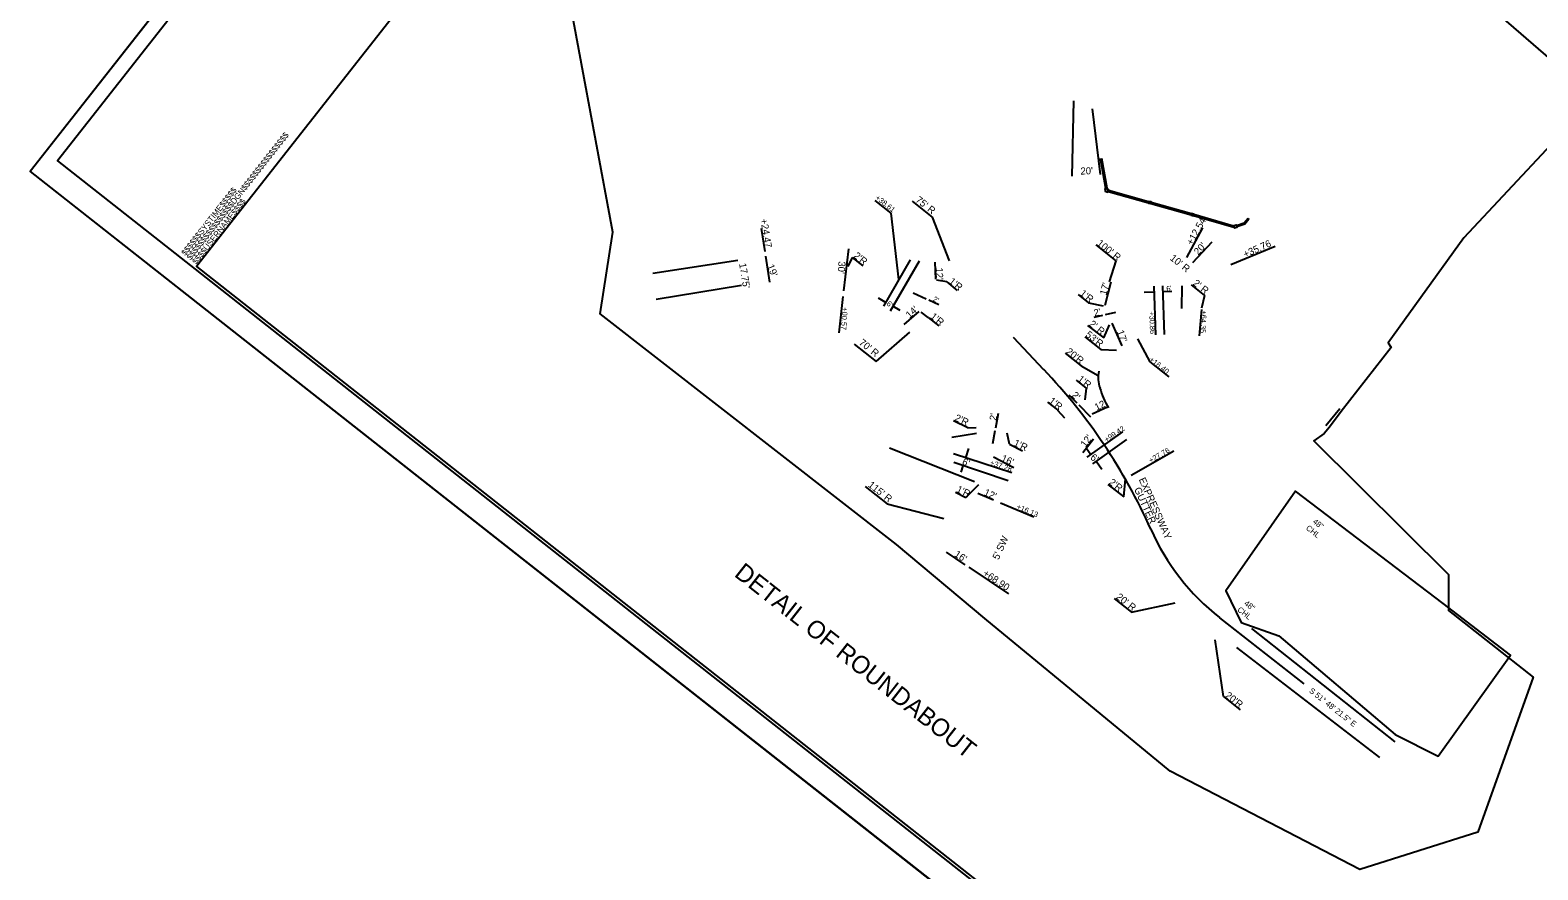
# Model space of a CAD drawing. Extents: x 556999 to 558602, y 505955 to 507732.
# Drawn here: x 556999 to 558063, y 506548 to 507140 of the extents above; entities that cross this region are included whole.
import ezdxf

# ---------------------------------------------------------------- set-up
doc = ezdxf.new("R2010")
doc.units = 0
for name, color, linetype in [('Default', 7, 'Continuous'), ('Exist Roads EOP', 7, 'Continuous'), ('Prop Dimension', 7, 'Continuous'), ('Prop Dimension Text', 7, 'Continuous'), ('Prop Horizontal Alignment', 7, 'Continuous'), ('Prop Horizontal Alignment Direction Label', 7, 'Continuous'), ('Prop Paint Stripe', 7, 'Continuous'), ('Sheet Border Standard 30in CELL', 7, 'Continuous'), ('Sheet Clip Boundary CELL', 7, 'Continuous'), ('Sheet Cutting Line CELL', 7, 'Continuous'), ('Sheet Plot Border Inside CELL', 7, 'Continuous'), ('Sheet Plot Border Outside CELL', 7, 'Continuous')]:
    doc.layers.add(name, color=color, linetype=linetype)

msp = doc.modelspace()

# ---------------------------------------------------------------- linework, layer by layer
at = {"layer": 'Default'}
for p, q in [((557754.1, 507049.3), (557757.8, 507028.2)), ((557755, 507049.4), (557758.7, 507028.4)), ((557759.8, 507025.9), (557788.1, 507017.8)), ((557760, 507026.8), (557788.2, 507018.7)), ((557789.8, 507017.4), (557818.2, 507009.3)), ((557790.1, 507018.3), (557818.5, 507010.2)), ((557820, 507008.8), (557848.5, 507000.6)), ((557820.2, 507009.7), (557848.2, 507001.7))]:
    msp.add_line(p, q, dxfattribs=at)
for points in [[(557757.4, 507027.9), (557757.7, 507026), (557759.5, 507025.4), (557759.9, 507027.1), (557759.1, 507027.2), (557759, 507028.2), (557757.4, 507027.9)], [(557788.2, 507017.6), (557789.7, 507017.3), (557790.1, 507018.4), (557788.5, 507018.8), (557788.2, 507017.6)], [(557818.3, 507009), (557819.9, 507008.6), (557820.2, 507009.7), (557818.6, 507010.2), (557818.3, 507009)], [(557848.3, 507001.8), (557850, 507002.2), (557850.5, 507000.5), (557848.8, 507000), (557848.3, 507001.8)], [(557850.3, 507001.8), (557855.8, 507003.6), (557858.4, 507007)], [(557850.5, 507001.1), (557856.2, 507003), (557859, 507006.5)]]:
    msp.add_lwpolyline(points, dxfattribs=at)
at = {"layer": 'Exist Roads EOP'}
for p, q in [((557734.4, 507036.7), (557735.4, 507089.8)), ((557754.4, 507037.8), (557748.6, 507084.1)), ((557858.4, 507007), (557859, 507006.5)), ((557498.4, 506977.2), (557438.5, 506968)), ((557501, 506959.6), (557440.7, 506949.6)), ((557860.9, 506717.6), (557962, 506637.8)), ((557850.3, 506704.2), (557951.1, 506626.6))]:
    msp.add_line(p, q, dxfattribs=at)
at = {"layer": 'Prop Dimension'}
for p, q in [((557606.7, 507010.6), (557595.3, 507019.5)), ((557612, 506963.7), (557606.7, 507010.6)), ((557514.8, 506999.7), (557517.4, 506983.4)), ((557815.3, 506979.2), (557826.6, 507000.2)), ((557846.4, 506974.4), (557877.6, 506987.2)), ((557517.9, 506980.2), (557520.7, 506961.8)), ((557576.5, 506985.4), (557573.1, 506955.8)), ((557579.2, 506979.3), (557576, 506972.9)), ((557579.2, 506979.3), (557586.6, 506973.4)), ((557637.5, 506976), (557637.8, 506964)), ((557645.8, 506962), (557638.6, 506963.2)), ((557645.8, 506962), (557653.3, 506956.1)), ((557785.1, 506954.8), (557792.4, 506955)), ((557798.4, 506955.2), (557804.6, 506955.4)), ((557811.7, 506959.3), (557811.4, 506943.3)), ((557818.4, 506959.9), (557827.8, 506952.4)), ((557572.6, 506951.7), (557569.7, 506926.2)), ((557602.5, 506947.7), (557597.7, 506950.5)), ((557612.9, 506942), (557607.9, 506944.9)), ((557622.1, 506954.3), (557631.4, 506950.1)), ((557633.1, 506949.4), (557640.3, 506946.2)), ((557738.5, 506953.1), (557745.9, 506947.3)), ((557745.9, 506947.3), (557756.3, 506945.1)), ((557827.8, 506952.4), (557825.5, 506943.5)), ((557615.8, 506932.1), (557626.4, 506941.1)), ((557632.8, 506936.9), (557627.7, 506940.8)), ((557632.8, 506936.9), (557640.2, 506931.1)), ((557755.8, 506938.3), (557749.7, 506936.9)), ((557764.8, 506940.5), (557757.6, 506938.8)), ((557825.6, 506942.5), (557823.9, 506924.1)), ((557743.2, 506923.3), (557754.6, 506914.4)), ((557745.2, 506931.4), (557756.7, 506922.5)), ((557756.7, 506922.5), (557760.6, 506931.8)), ((557754.6, 506914.4), (557765.6, 506913.9)), ((557780.4, 506921.9), (557789.1, 506905.6)), ((557729.3, 506911.7), (557740.7, 506902.8)), ((557740.7, 506902.8), (557752.6, 506896.1)), ((557737.2, 506892.7), (557744.2, 506887.2)), ((557737.9, 506876.5), (557732.3, 506882.3)), ((557744.2, 506887.2), (557743.2, 506878.9)), ((557716.9, 506877.3), (557723.9, 506871.8)), ((557723.9, 506871.7), (557729, 506866.3)), ((557747.5, 506866.6), (557739.2, 506875.2)), ((557913.2, 506860.9), (557923.3, 506872.9)), ((557660.8, 506859.2), (557650.6, 506864.2)), ((557660.8, 506859.2), (557666.6, 506859.4)), ((557680.4, 506859.2), (557682.3, 506869.4)), ((557678.3, 506848.2), (557680, 506857.3)), ((557690.1, 506847.7), (557688.4, 506855.5)), ((557659.4, 506838), (557661.5, 506844.5)), ((557690.1, 506847.7), (557699.4, 506843)), ((557744.1, 506845), (557747.4, 506840.4)), ((557775.9, 506825.7), (557806, 506842.9)), ((557656.1, 506827.9), (557657.5, 506832.3)), ((557751.4, 506835.5), (557755.3, 506830.1)), ((557659.3, 506810), (557668.5, 506819.2)), ((557759.6, 506819.3), (557770.7, 506810.6)), ((557770.7, 506810.6), (557772, 506823.3)), ((557651.9, 506813.7), (557659.3, 506810)), ((557667.8, 506813.1), (557678.9, 506808.4)), ((557683.7, 506806.3), (557707.2, 506796.3)), ((557645.4, 506771.6), (557658.7, 506762.6)), ((557661.5, 506760.8), (557689.5, 506742))]:
    msp.add_line(p, q, dxfattribs=at)
for centre, radius, start, end in [((557772.6, 506894.5), 20, 166.7873, 201.4413), ((557815.1, 506905), 63.7, 196.2498, 209.8717)]:
    msp.add_arc(centre, radius, start, end, dxfattribs=at)
at = {"layer": 'Prop Dimension Text'}
for p, q in [((557621.5, 507019), (557635.6, 507007.8)), ((557635.6, 507007.8), (557647.5, 506976.9)), ((557751, 506988.3), (557765.1, 506977)), ((557832.8, 506990.1), (557819.3, 506975.4)), ((557765.1, 506977), (557760.5, 506962.2)), ((557761.5, 506961.9), (557757.3, 506945.5)), ((557596.1, 506906), (557619.8, 506926.7)), ((557762.3, 506932.9), (557769.4, 506916.9)), ((557580.6, 506918.2), (557596.1, 506906)), ((557789.1, 506905.6), (557802.6, 506895)), ((557748.4, 506869.1), (557759.3, 506873.9)), ((557649.4, 506852.6), (557666.9, 506855.4)), ((557749.5, 506851.2), (557741.9, 506841.5)), ((557665.5, 506821.1), (557605.4, 506844.8)), ((557678.9, 506838.7), (557693.2, 506831.2)), ((557588.3, 506817.7), (557603.8, 506805.5)), ((557603.8, 506805.5), (557643.8, 506795.3)), ((557764, 506738.8), (557776.2, 506729.2)), ((557776.2, 506729.2), (557807, 506735.7)), ((557841, 506669.8), (557835.2, 506709.7)), ((557841, 506669.8), (557852.9, 506660.3))]:
    msp.add_line(p, q, dxfattribs=at)
at = {"layer": 'Prop Horizontal Alignment'}
for p, q in [((557692.6, 506923.1), (557714.2, 506900.3)), ((557838.4, 506725.3), (557897.7, 506678.7))]:
    msp.add_line(p, q, dxfattribs=at)
for centre, radius, start, end in [((557424.6, 506624.5), 400, 24.0786, 43.6077), ((557940.4, 506855), 165, 204.0786, 231.806)]:
    msp.add_arc(centre, radius, start, end, dxfattribs=at)
at = {"layer": 'Prop Paint Stripe'}
for p, q in [((557620, 506977.7), (557601.1, 506945)), ((557626.3, 506976.6), (557606, 506941.5)), ((557793.4, 506924.8), (557792.3, 506959)), ((557799.4, 506925), (557798.3, 506959.2)), ((557745, 506838.5), (557770.1, 506856.3)), ((557748.8, 506833.8), (557773, 506851)), ((557691.7, 506827.5), (557650.6, 506840.9)), ((557689.2, 506821.9), (557650.8, 506834.6))]:
    msp.add_line(p, q, dxfattribs=at)
at = {"layer": 'Sheet Border Standard 30in CELL'}
msp.add_lwpolyline([(558579, 506891.5), (557635.7, 507633.3), (557116.5, 506973), (558059.7, 506231.2)], close=True, dxfattribs=at)
at = {"layer": 'Sheet Clip Boundary CELL'}
for points in [[(557670.2, 507466.2), (558103.1, 507091.8), (558010.6, 506993.1), (557957.2, 506919.1), (557959.4, 506915.7), (557924.2, 506870.7), (557915.9, 506859.7), (557912.1, 506855.2), (557904.9, 506850.1), (557999.9, 506755.8), (557999.9, 506730.4), (558059.5, 506683.3), (558020.5, 506574.1), (557937.4, 506547.8), (557803.4, 506617.1), (557672.6, 506724.6), (557610.3, 506776.9), (557401.4, 506939.6), (557410.2, 506997.1), (557374.3, 507190.6)], [(557996.1, 506735.4), (557892, 506814.4), (557842.7, 506744.3), (557853.6, 506721.9), (557880.2, 506712.5), (557962.3, 506642.9), (557992.5, 506627.7), (558043.5, 506698.8)]]:
    msp.add_lwpolyline(points, close=True, dxfattribs=at)
at = {"layer": 'Sheet Cutting Line CELL'}
for p, q in [((557543.1, 507731.6), (556999.1, 507039.9)), ((556999.1, 507039.9), (558058.1, 506207.1))]:
    msp.add_line(p, q, dxfattribs=at)
at = {"layer": 'Sheet Plot Border Inside CELL'}
msp.add_lwpolyline([(558588.1, 506886.9), (557540.2, 507711), (557018.4, 507047.5), (558066.3, 506223.4)], close=True, dxfattribs=at)
at = {"layer": 'Sheet Plot Border Outside CELL'}
msp.add_lwpolyline([(558602.1, 506898.8), (557543.1, 507731.6), (556999.1, 507039.9), (558058.1, 506207.1)], close=True, dxfattribs=at)

# ---------------------------------------------------------------- texts
at = {"layer": 'Default'}
for s, p in [('CHL', (557898.9, 506787.8)), ('48" ', (557903.7, 506792.3)), ('CHL', (557850.5, 506730.2)), ('48" ', (557855.3, 506734.7))]:
    msp.add_text(s, height=4, rotation=321.6667, dxfattribs=at).set_placement(p)
at = {"layer": 'Prop Dimension'}
for s, height, rotation, p in [("20'", 5, 2.0267, (557740.3, 507037.7)), ("2'R", 5, 321.3211, (557579.7, 506979.7)), ("12'", 5, 272.0176, (557638.1, 506972.1)), ("1'R", 5, 321.3211, (557646.9, 506961.6)), ("1'R", 5, 321.896, (557739.3, 506953.1)), ("17'", 5, 74.486, (557758.4, 506952.3)), ("6'", 3.75, 9.8988, (557801.1, 506955.2)), ("6'", 3.75, 321.3322, (557603, 506946.1)), ("14'", 5, 41.5358, (557619.6, 506936.1)), ("2'", 3.75, 334.8598, (557635.7, 506948.7)), ('+00.57', 3.75, 265.9094, (557572.3, 506944.2)), ("1'R", 5, 321.3211, (557633.8, 506936.9)), ("2'", 5, 13.6398, (557750.2, 506937.6)), ('+30.86', 3.75, 272.1966, (557788.7, 506941.2)), ('+64.35', 3.75, 266.4186, (557825.6, 506942)), ("53'R", 5, 321.896, (557743.3, 506924)), ("17'", 5, 289.8655, (557765.7, 506927.1)), ("20'R", 5, 321.896, (557729.5, 506912.1)), ("1'R", 5, 321.896, (557737.7, 506892.7)), ("2'", 5, 316.1819, (557733.5, 506881.6)), ("1'R", 5, 321.896, (557717.4, 506877.3)), ("12'", 5, 25.9634, (557751.6, 506871.1)), ("2'R", 5, 335.3658, (557651, 506864.5)), ("2'", 5, 80.6948, (557680.8, 506864)), ('+99.42', 3.75, 33.9385, (557758.6, 506848.8)), ("1'R", 5, 335.3658, (557692.6, 506846.7)), ("12'", 5, 53.0558, (557743.7, 506845)), ("16'", 5, 336.226, (557683.8, 506835.9)), ("6'", 5, 322.8202, (557746.7, 506837.4)), ('+27.76', 3.75, 30.2326, (557789.8, 506834.2)), ("6'", 5, 335.3658, (557656.2, 506833.6)), ('+37.28', 3.75, 341.5363, (557676, 506833.1)), ("1'R", 5, 335.3658, (557652.2, 506814.1)), ("2'R", 5, 321.896, (557759.8, 506819.9)), ("12'", 5, 335.3658, (557671.6, 506811.9)), ('+16.13', 3.75, 337.0119, (557694.7, 506802.2)), ('DETAIL OF ROUNDABOUT', 12.5, 321.8181, (557495.2, 506755)), ("16'", 5, 326.369, (557650.7, 506768.9)), ('+68.90', 5, 326.369, (557670.9, 506755.4))]:
    msp.add_text(s, height=height, rotation=rotation, dxfattribs=at).set_placement(p)
at = {"layer": 'Prop Dimension Text'}
for s, height, rotation, p in [('+38.61', 3.75, 321.7054, (557595.1, 507020.7)), ("75' R", 5, 321.7054, (557623.4, 507019)), ('+24.47', 5, 279.3234, (557514.3, 507006.2)), ('+12.54', 5, 60.9094, (557819, 506987.5)), ("100' R", 5, 321.7054, (557751.3, 506988.4)), ("20'", 5, 46.8646, (557823.3, 506980.6)), ('+35.76', 5, 23.8346, (557856.4, 506979)), ("30'", 5, 265.7494, (557569.5, 506976.7)), ("10' R", 5, 321.7054, (557802.9, 506978)), ("17.75'", 5, 279.3234, (557499.3, 506974.9)), ("19'", 5, 291.1287, (557519, 506973.4)), ("2' R", 5, 321.7054, (557819.1, 506960.3)), ("2' R", 5, 321.7054, (557745.8, 506931.5)), ("70' R", 5, 321.7054, (557583.5, 506918.4)), ('+16.40', 3.75, 321.7054, (557788.4, 506906.7)), ("115' R", 5, 321.7054, (557589.9, 506818.1)), ('GUTTER', 5, 294.566, (557777.9, 506815.9)), ('EXPRESSWAY', 5, 293.8861, (557781.2, 506822.8)), ('SW', 5, 65.9495, (557685.1, 506771.6)), ("5'", 5, 65.9495, (557682.4, 506765.7)), ("20' R", 5, 321.7054, (557764.9, 506739.1)), ("20'R", 5, 321.9042, (557841.8, 506669.6))]:
    msp.add_text(s, height=height, rotation=rotation, dxfattribs=at).set_placement(p)
at = {"layer": 'Prop Horizontal Alignment Direction Label'}
msp.add_text('S 51%%d 48\' 21.5" E', height=4, rotation=321.806, dxfattribs=at).set_placement((557901.2, 506673))
at = {"layer": 'Sheet Border Standard 30in CELL'}
for s, p in [('$$$$$$$$$$$$$$$$DGN$$$$$$$$$$$$$$$$', (557112.4, 506977.1)), ('$$$$$$SYSTIME$$$$$', (557108.7, 506980.2)), ('$$$$USERNAME$$$$', (557116.4, 506974))]:
    msp.add_text(s, height=4.2, rotation=51.8181, dxfattribs=at).set_placement(p)

doc.saveas('drawing.dxf')
